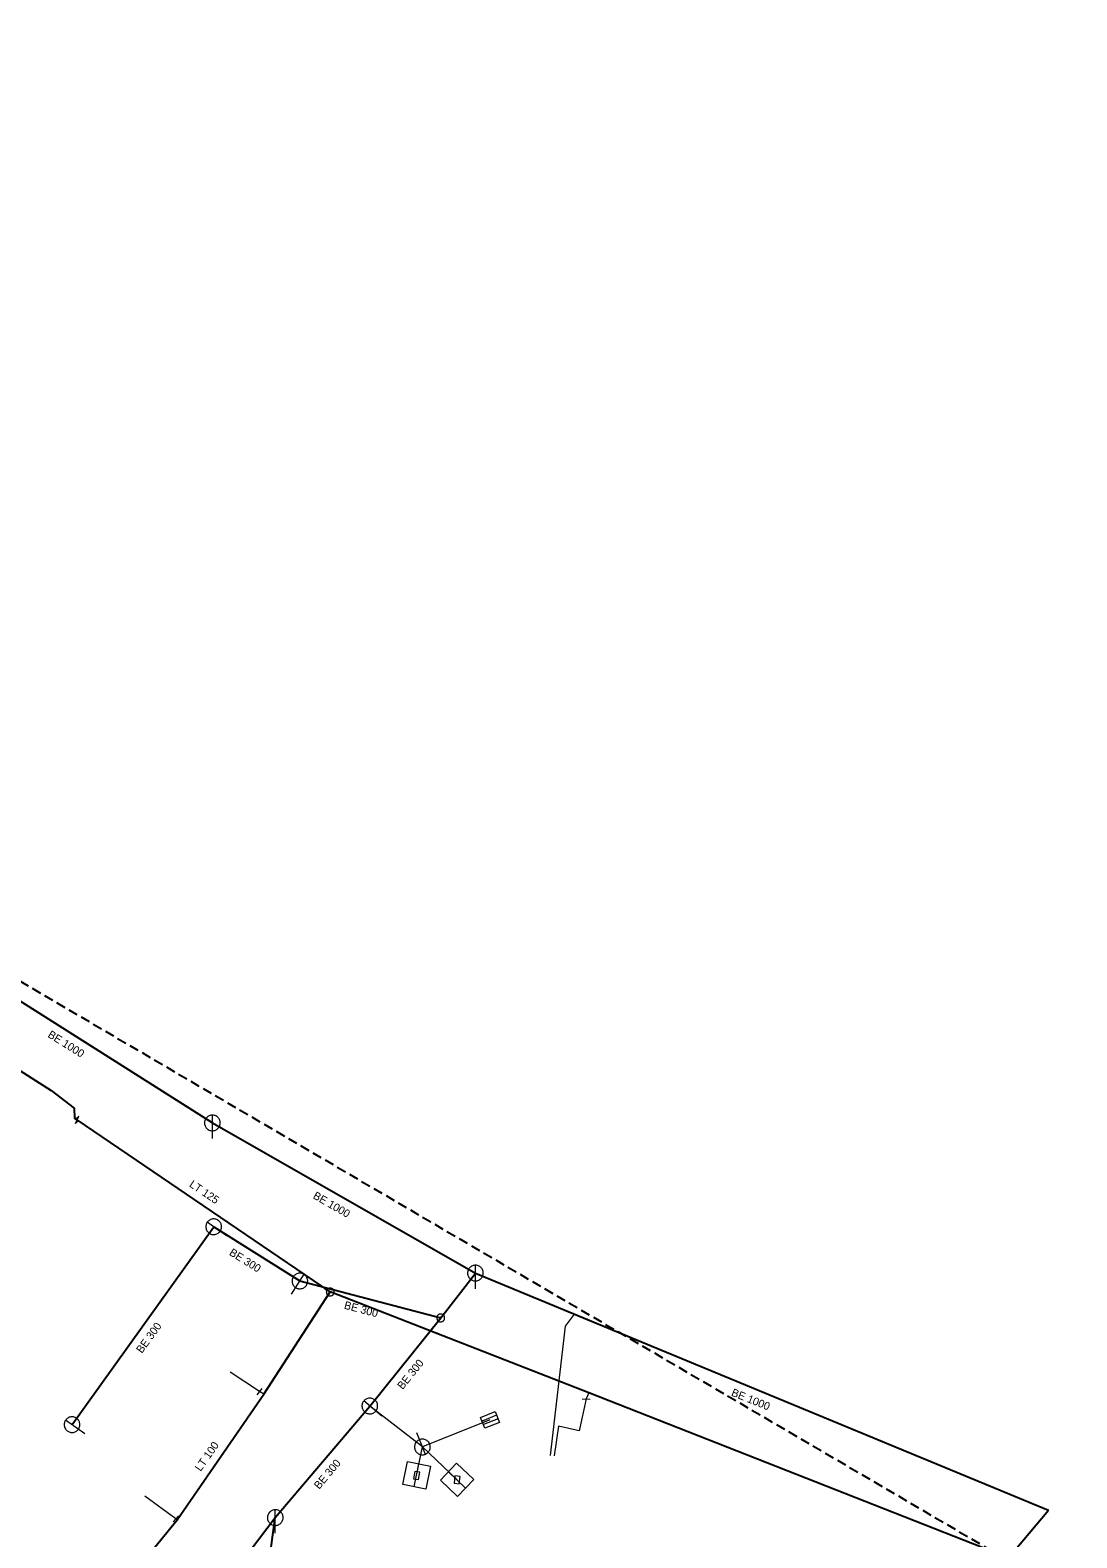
# Model space of a CAD drawing. Extents: x -791337 to -790755, y -988454 to -987923.
# Drawn here: x -791023.2 to -790890, y -988115.1 to -987923.1 of the extents above; entities that cross this region are included whole.
import ezdxf

# ---------------------------------------------------------------- set-up
doc = ezdxf.new("R2010")
doc.units = 0
doc.header["$LTSCALE"] = 0.4
doc.linetypes.add('MEDIUM_DASHED', pattern=[4.5, 3, -1.5])
for name, color, linetype, lineweight in [('1', 7, 'Continuous', 13), ('11', 7, 'Continuous', 13), ('13', 7, 'Continuous', 13), ('14', 7, 'Continuous', 25), ('17', 7, 'Continuous', 25), ('22', 7, 'Continuous', 13), ('23', 7, 'Continuous', 13), ('31', 7, 'Continuous', 13), ('34', 7, 'Continuous', 13), ('47', 7, 'Continuous', 13), ('63', 7, 'MEDIUM_DASHED', 25)]:
    doc.layers.add(name, color=color, linetype=linetype, lineweight=lineweight)

msp = doc.modelspace()

# ---------------------------------------------------------------- linework, layer by layer
at = {"layer": '1'}
for points in [[(-790974.289, -988106.68), (-790974.43, -988107.629), (-790973.78, -988107.719), (-790973.64, -988106.77)], [(-790969.16, -988107.25), (-790969.281, -988108.207), (-790968.631, -988108.287), (-790968.509, -988107.332)]]:
    msp.add_lwpolyline(points, close=True, dxfattribs=at)
at = {"layer": '11'}
for p, q in [((-790973.309, -988103.579), (-790980, -988098.359)), ((-790964.71, -988100.129), (-790973.309, -988103.579)), ((-790974.039, -988107.199), (-790973.309, -988103.579)), ((-790968.899, -988107.77), (-790973.309, -988103.579))]:
    msp.add_line(p, q, dxfattribs=at)
msp.add_lwpolyline([(-790956.991, -988104.669), (-790955.074, -988088.182), (-790953.942, -988086.649)], dxfattribs=at)
at = {"layer": '13'}
for p, q in [((-790994.059, -988096.529), (-790997.761, -988094.041)), ((-790993.489, -988096.87), (-790994.059, -988096.529)), ((-790952.1, -988096.67), (-790952.459, -988097.459)), ((-791004.699, -988112.739), (-791008.625, -988109.853))]:
    msp.add_line(p, q, dxfattribs=at)
msp.add_lwpolyline([(-790952.459, -988097.459), (-790953.335, -988101.511), (-790955.997, -988100.945), (-790956.52, -988104.695)], dxfattribs=at)
at = {"layer": '14'}
for p, q in [((-791000.039, -988062.309), (-790966.559, -988081.43)), ((-791017.9, -988100.734), (-790999.87, -988075.53)), ((-790999.87, -988075.53), (-790988.902, -988082.432)), ((-790966.559, -988081.43), (-790893.6, -988111.609)), ((-790980, -988098.359), (-790970.978, -988087.145)), ((-790995.768, -988140.376), (-790992.035, -988112.568))]:
    msp.add_line(p, q, dxfattribs=at)
at = {"layer": '14', "lineweight": 13}
msp.add_line((-791004.537, -988112.846), (-791004.699, -988112.739), dxfattribs=at)
at = {"layer": '14'}
for points in [[(-791048.694, -988062.718), (-791034.09, -988040.71), (-791000.039, -988062.309)], [(-790988.902, -988082.432), (-790970.978, -988087.145), (-790966.559, -988081.43)], [(-791003.034, -988127.09), (-790992.035, -988112.568), (-790980, -988098.359)], [(-790905.94, -988138.22), (-790903.94, -988123.91), (-790893.6, -988111.609)]]:
    msp.add_lwpolyline(points, dxfattribs=at)
at = {"layer": '17'}
msp.add_line((-790985.039, -988083.809), (-791017.239, -988061.899), dxfattribs=at)
for points in [[(-791034.776, -988049.416), (-791034.559, -988049.35), (-791029.19, -988052.69), (-791020.559, -988058.18), (-791017.64, -988060.43), (-791017.59, -988061.71), (-791017.239, -988061.899)], [(-791015.996, -988126.782), (-791014.379, -988124.914), (-791004.537, -988112.846), (-790993.489, -988096.87), (-790985.039, -988083.809)], [(-790868.789, -988131.909), (-790898.061, -988117.949), (-790952.1, -988096.67), (-790985.039, -988083.809)]]:
    msp.add_lwpolyline(points, dxfattribs=at)
at = {"layer": '22'}
for p, q in [((-791000.039, -988064.309), (-791000.038, -988061.309)), ((-790998.242, -988076.693), (-791000.682, -988074.948)), ((-790966.559, -988083.43), (-790966.558, -988080.43)), ((-790989.967, -988084.125), (-790988.369, -988081.586)), ((-790978.473, -988099.651), (-790980.762, -988097.712)), ((-790963.862, -988099.526), (-790965.718, -988100.271)), ((-791016.272, -988101.897), (-791018.712, -988100.152)), ((-790963.676, -988099.99), (-790965.532, -988100.735)), ((-790974.053, -988101.722), (-790972.936, -988104.506)), ((-790974.335, -988108.669), (-790973.741, -988105.728)), ((-790967.811, -988108.802), (-790969.986, -988106.736)), ((-790992.035, -988114.568), (-790992.034, -988111.568))]:
    msp.add_line(p, q, dxfattribs=at)
for points in [[(-790999.039, -988062.309), (-790999.044, -988062.2), (-790999.062, -988062.092), (-790999.092, -988061.986), (-790999.132, -988061.885), (-790999.184, -988061.788), (-790999.246, -988061.698), (-790999.318, -988061.615), (-790999.398, -988061.541), (-790999.486, -988061.475), (-790999.58, -988061.42), (-790999.68, -988061.375), (-790999.785, -988061.342), (-790999.892, -988061.32), (-791000.001, -988061.31), (-791000.111, -988061.312), (-791000.219, -988061.326), (-791000.326, -988061.351), (-791000.429, -988061.388), (-791000.527, -988061.437), (-791000.619, -988061.495), (-791000.705, -988061.564), (-791000.782, -988061.641), (-791000.851, -988061.727), (-791000.91, -988061.819), (-791000.958, -988061.917), (-791000.995, -988062.02), (-791001.021, -988062.127), (-791001.035, -988062.235), (-791001.038, -988062.345), (-791001.028, -988062.454), (-791001.007, -988062.561), (-791000.973, -988062.665), (-791000.929, -988062.765), (-791000.874, -988062.86), (-791000.808, -988062.948), (-791000.734, -988063.028), (-791000.651, -988063.1), (-791000.561, -988063.162), (-791000.465, -988063.214), (-791000.363, -988063.255), (-791000.258, -988063.285), (-791000.15, -988063.303), (-791000.04, -988063.309), (-790999.931, -988063.303), (-790999.823, -988063.285), (-790999.718, -988063.256), (-790999.616, -988063.215), (-790999.519, -988063.163), (-790999.429, -988063.101), (-790999.346, -988063.03), (-790999.271, -988062.95), (-790999.206, -988062.862), (-790999.15, -988062.768), (-790999.106, -988062.668), (-790999.072, -988062.564), (-790999.05, -988062.456), (-790999.04, -988062.347)], [(-790999.287, -988074.716), (-790999.379, -988074.658), (-790999.478, -988074.61), (-790999.581, -988074.572), (-790999.687, -988074.546), (-790999.796, -988074.532), (-790999.905, -988074.53), (-791000.015, -988074.54), (-791000.121, -988074.562), (-791000.226, -988074.596), (-791000.326, -988074.64), (-791000.42, -988074.695), (-791000.508, -988074.761), (-791000.589, -988074.836), (-791000.66, -988074.918), (-791000.722, -988075.009), (-791000.774, -988075.105), (-791000.816, -988075.207), (-791000.846, -988075.312), (-791000.863, -988075.42), (-791000.869, -988075.529), (-791000.863, -988075.639), (-791000.845, -988075.746), (-791000.815, -988075.852), (-791000.775, -988075.954), (-791000.723, -988076.05), (-791000.661, -988076.14), (-791000.589, -988076.223), (-791000.509, -988076.298), (-791000.421, -988076.363), (-791000.327, -988076.419), (-791000.227, -988076.464), (-791000.123, -988076.497), (-791000.016, -988076.519), (-790999.907, -988076.529), (-790999.797, -988076.527), (-790999.689, -988076.513), (-790999.582, -988076.488), (-790999.479, -988076.451), (-790999.381, -988076.403), (-790999.288, -988076.344), (-790999.203, -988076.276), (-790999.125, -988076.198), (-790999.056, -988076.112), (-790998.998, -988076.02), (-790998.95, -988075.922), (-790998.912, -988075.82), (-790998.886, -988075.713), (-790998.872, -988075.604), (-790998.87, -988075.494), (-790998.879, -988075.386), (-790998.901, -988075.278), (-790998.935, -988075.174), (-790998.979, -988075.074), (-790999.034, -988074.98), (-790999.099, -988074.892), (-790999.174, -988074.811), (-790999.257, -988074.739)], [(-790965.559, -988081.43), (-790965.564, -988081.321), (-790965.582, -988081.213), (-790965.612, -988081.107), (-790965.652, -988081.006), (-790965.704, -988080.909), (-790965.766, -988080.819), (-790965.838, -988080.736), (-790965.918, -988080.662), (-790966.006, -988080.596), (-790966.1, -988080.541), (-790966.2, -988080.496), (-790966.305, -988080.463), (-790966.412, -988080.441), (-790966.521, -988080.431), (-790966.631, -988080.433), (-790966.739, -988080.447), (-790966.846, -988080.472), (-790966.949, -988080.509), (-790967.047, -988080.558), (-790967.139, -988080.616), (-790967.225, -988080.685), (-790967.302, -988080.762), (-790967.371, -988080.848), (-790967.43, -988080.94), (-790967.478, -988081.038), (-790967.515, -988081.141), (-790967.541, -988081.248), (-790967.555, -988081.356), (-790967.558, -988081.466), (-790967.548, -988081.575), (-790967.527, -988081.682), (-790967.493, -988081.786), (-790967.449, -988081.886), (-790967.394, -988081.981), (-790967.328, -988082.069), (-790967.254, -988082.149), (-790967.171, -988082.221), (-790967.081, -988082.283), (-790966.985, -988082.335), (-790966.883, -988082.376), (-790966.778, -988082.406), (-790966.67, -988082.424), (-790966.56, -988082.43), (-790966.451, -988082.424), (-790966.343, -988082.406), (-790966.238, -988082.377), (-790966.136, -988082.336), (-790966.039, -988082.284), (-790965.949, -988082.222), (-790965.866, -988082.151), (-790965.791, -988082.071), (-790965.726, -988081.983), (-790965.67, -988081.889), (-790965.626, -988081.789), (-790965.592, -988081.685), (-790965.57, -988081.577), (-790965.56, -988081.468)], [(-790988.055, -988082.964), (-790988.002, -988082.869), (-790987.96, -988082.768), (-790987.929, -988082.662), (-790987.909, -988082.556), (-790987.901, -988082.446), (-790987.906, -988082.337), (-790987.923, -988082.228), (-790987.951, -988082.123), (-790987.99, -988082.02), (-790988.041, -988081.923), (-790988.101, -988081.832), (-790988.173, -988081.748), (-790988.251, -988081.673), (-790988.338, -988081.606), (-790988.433, -988081.549), (-790988.531, -988081.504), (-790988.635, -988081.468), (-790988.742, -988081.444), (-790988.851, -988081.433), (-790988.96, -988081.434), (-790989.07, -988081.446), (-790989.176, -988081.47), (-790989.28, -988081.506), (-790989.379, -988081.553), (-790989.472, -988081.61), (-790989.558, -988081.678), (-790989.637, -988081.754), (-790989.706, -988081.838), (-790989.766, -988081.93), (-790989.816, -988082.028), (-790989.855, -988082.13), (-790989.882, -988082.236), (-790989.898, -988082.344), (-790989.902, -988082.454), (-790989.893, -988082.563), (-790989.873, -988082.67), (-790989.841, -988082.776), (-790989.798, -988082.876), (-790989.744, -988082.971), (-790989.68, -988083.06), (-790989.607, -988083.141), (-790989.525, -988083.214), (-790989.435, -988083.278), (-790989.34, -988083.331), (-790989.239, -988083.373), (-790989.134, -988083.404), (-790989.026, -988083.424), (-790988.916, -988083.432), (-790988.807, -988083.427), (-790988.699, -988083.411), (-790988.593, -988083.383), (-790988.491, -988083.344), (-790988.394, -988083.294), (-790988.303, -988083.233), (-790988.219, -988083.163), (-790988.143, -988083.083), (-790988.076, -988082.996)], [(-790979.353, -988097.596), (-790979.44, -988097.53), (-790979.534, -988097.474), (-790979.634, -988097.428), (-790979.737, -988097.393), (-790979.845, -988097.37), (-790979.953, -988097.36), (-790980.063, -988097.361), (-790980.172, -988097.374), (-790980.279, -988097.399), (-790980.381, -988097.435), (-790980.48, -988097.482), (-790980.573, -988097.541), (-790980.659, -988097.608), (-790980.738, -988097.685), (-790980.807, -988097.77), (-790980.866, -988097.862), (-790980.916, -988097.959), (-790980.955, -988098.062), (-790980.981, -988098.168), (-790980.996, -988098.276), (-790980.999, -988098.386), (-790980.99, -988098.495), (-790980.969, -988098.603), (-790980.937, -988098.708), (-790980.893, -988098.807), (-790980.838, -988098.902), (-790980.773, -988098.991), (-790980.7, -988099.072), (-790980.617, -988099.144), (-790980.528, -988099.207), (-790980.432, -988099.26), (-790980.331, -988099.302), (-790980.226, -988099.333), (-790980.118, -988099.352), (-790980.009, -988099.359), (-790979.9, -988099.354), (-790979.791, -988099.337), (-790979.686, -988099.308), (-790979.584, -988099.269), (-790979.487, -988099.217), (-790979.396, -988099.157), (-790979.312, -988099.086), (-790979.237, -988099.006), (-790979.171, -988098.919), (-790979.115, -988098.825), (-790979.069, -988098.726), (-790979.034, -988098.622), (-790979.011, -988098.514), (-790979.001, -988098.405), (-790979.001, -988098.296), (-790979.014, -988098.187), (-790979.039, -988098.081), (-790979.074, -988097.977), (-790979.122, -988097.879), (-790979.18, -988097.786), (-790979.248, -988097.699), (-790979.324, -988097.621)], [(-790963.49, -988100.454), (-790965.346, -988101.199), (-790965.904, -988099.807), (-790964.048, -988099.062)], [(-791017.317, -988099.92), (-791017.409, -988099.862), (-791017.508, -988099.814), (-791017.611, -988099.776), (-791017.717, -988099.75), (-791017.826, -988099.736), (-791017.935, -988099.734), (-791018.045, -988099.744), (-791018.151, -988099.766), (-791018.256, -988099.8), (-791018.356, -988099.844), (-791018.45, -988099.899), (-791018.538, -988099.965), (-791018.619, -988100.04), (-791018.69, -988100.122), (-791018.752, -988100.213), (-791018.804, -988100.309), (-791018.846, -988100.411), (-791018.876, -988100.516), (-791018.893, -988100.624), (-791018.899, -988100.733), (-791018.893, -988100.843), (-791018.875, -988100.95), (-791018.845, -988101.056), (-791018.805, -988101.158), (-791018.753, -988101.254), (-791018.691, -988101.344), (-791018.619, -988101.427), (-791018.539, -988101.502), (-791018.451, -988101.567), (-791018.357, -988101.623), (-791018.257, -988101.668), (-791018.153, -988101.701), (-791018.046, -988101.723), (-791017.937, -988101.733), (-791017.827, -988101.731), (-791017.719, -988101.717), (-791017.612, -988101.692), (-791017.509, -988101.655), (-791017.411, -988101.607), (-791017.318, -988101.548), (-791017.233, -988101.48), (-791017.155, -988101.402), (-791017.086, -988101.316), (-791017.028, -988101.224), (-791016.98, -988101.126), (-791016.942, -988101.024), (-791016.916, -988100.917), (-791016.902, -988100.808), (-791016.9, -988100.698), (-791016.909, -988100.59), (-791016.931, -988100.482), (-791016.965, -988100.378), (-791017.009, -988100.278), (-791017.064, -988100.184), (-791017.129, -988100.096), (-791017.204, -988100.015), (-791017.287, -988099.943)], [(-790974.237, -988103.95), (-790974.191, -988104.049), (-790974.134, -988104.143), (-790974.066, -988104.23), (-790973.992, -988104.309), (-790973.907, -988104.38), (-790973.816, -988104.44), (-790973.719, -988104.49), (-790973.617, -988104.529), (-790973.51, -988104.558), (-790973.403, -988104.574), (-790973.293, -988104.578), (-790973.183, -988104.57), (-790973.076, -988104.55), (-790972.971, -988104.519), (-790972.87, -988104.476), (-790972.775, -988104.423), (-790972.685, -988104.36), (-790972.603, -988104.287), (-790972.53, -988104.205), (-790972.466, -988104.117), (-790972.412, -988104.021), (-790972.369, -988103.921), (-790972.337, -988103.815), (-790972.317, -988103.708), (-790972.309, -988103.599), (-790972.313, -988103.49), (-790972.329, -988103.381), (-790972.356, -988103.276), (-790972.395, -988103.173), (-790972.445, -988103.075), (-790972.504, -988102.984), (-790972.574, -988102.9), (-790972.652, -988102.823), (-790972.739, -988102.756), (-790972.833, -988102.699), (-790972.931, -988102.652), (-790973.035, -988102.616), (-790973.142, -988102.592), (-790973.25, -988102.579), (-790973.36, -988102.579), (-790973.469, -988102.591), (-790973.576, -988102.614), (-790973.68, -988102.65), (-790973.779, -988102.696), (-790973.873, -988102.753), (-790973.959, -988102.819), (-790974.039, -988102.895), (-790974.109, -988102.979), (-790974.17, -988103.07), (-790974.22, -988103.167), (-790974.26, -988103.269), (-790974.288, -988103.375), (-790974.305, -988103.483), (-790974.308, -988103.592), (-790974.301, -988103.701), (-790974.281, -988103.81), (-790974.25, -988103.915)], [(-790975.805, -988108.372), (-790975.212, -988105.432), (-790972.271, -988106.025), (-790972.864, -988108.966)], [(-790968.844, -988109.89), (-790971.019, -988107.823), (-790968.952, -988105.649), (-790966.778, -988107.715)], [(-790991.035, -988112.568), (-790991.04, -988112.459), (-790991.058, -988112.351), (-790991.088, -988112.245), (-790991.128, -988112.144), (-790991.18, -988112.047), (-790991.242, -988111.957), (-790991.314, -988111.874), (-790991.394, -988111.8), (-790991.482, -988111.734), (-790991.576, -988111.679), (-790991.676, -988111.634), (-790991.781, -988111.601), (-790991.888, -988111.579), (-790991.997, -988111.569), (-790992.107, -988111.571), (-790992.215, -988111.585), (-790992.322, -988111.61), (-790992.425, -988111.647), (-790992.523, -988111.696), (-790992.615, -988111.754), (-790992.701, -988111.823), (-790992.778, -988111.9), (-790992.847, -988111.986), (-790992.906, -988112.078), (-790992.954, -988112.176), (-790992.991, -988112.279), (-790993.017, -988112.386), (-790993.031, -988112.494), (-790993.034, -988112.604), (-790993.024, -988112.713), (-790993.003, -988112.82), (-790992.969, -988112.924), (-790992.925, -988113.024), (-790992.87, -988113.119), (-790992.804, -988113.207), (-790992.73, -988113.287), (-790992.647, -988113.359), (-790992.557, -988113.421), (-790992.461, -988113.473), (-790992.359, -988113.514), (-790992.254, -988113.544), (-790992.146, -988113.562), (-790992.036, -988113.568), (-790991.927, -988113.562), (-790991.819, -988113.544), (-790991.714, -988113.515), (-790991.612, -988113.474), (-790991.515, -988113.422), (-790991.425, -988113.36), (-790991.342, -988113.289), (-790991.267, -988113.209), (-790991.202, -988113.121), (-790991.146, -988113.027), (-790991.102, -988112.927), (-790991.068, -988112.823), (-790991.046, -988112.715), (-790991.036, -988112.606)]]:
    msp.add_lwpolyline(points, close=True, dxfattribs=at)
at = {"layer": '23'}
msp.add_line((-790985.531, -988083.379), (-790985.639, -988083.543), dxfattribs=at)
for points in [[(-790985.558, -988083.596), (-790985.682, -988083.514), (-790985.754, -988083.348), (-790985.574, -988083.35), (-790985.45, -988083.433)], [(-790984.76, -988083.421), (-790984.806, -988083.394), (-790984.855, -988083.373), (-790984.904, -988083.358), (-790984.955, -988083.347), (-790985.007, -988083.341), (-790985.06, -988083.342), (-790985.112, -988083.347), (-790985.162, -988083.358), (-790985.212, -988083.374), (-790985.26, -988083.396), (-790985.306, -988083.422), (-790985.348, -988083.453), (-790985.387, -988083.488), (-790985.421, -988083.526), (-790985.452, -988083.568), (-790985.479, -988083.615), (-790985.499, -988083.661), (-790985.516, -988083.713), (-790985.527, -988083.762), (-790985.533, -988083.815), (-790985.531, -988083.868), (-790985.526, -988083.92), (-790985.514, -988083.972), (-790985.499, -988084.021), (-790985.478, -988084.068), (-790985.45, -988084.114), (-790985.42, -988084.155), (-790985.385, -988084.194), (-790985.345, -988084.229), (-790985.304, -988084.26), (-790985.259, -988084.286), (-790985.21, -988084.308), (-790985.16, -988084.324), (-790985.11, -988084.335), (-790985.058, -988084.339), (-790985.006, -988084.339), (-790984.953, -988084.334), (-790984.901, -988084.323), (-790984.852, -988084.306)], [(-790985.516, -988083.713), (-790985.527, -988083.762), (-790985.533, -988083.815), (-790985.531, -988083.868), (-790985.526, -988083.92), (-790985.514, -988083.972), (-790985.499, -988084.021), (-790985.478, -988084.068), (-790985.45, -988084.114), (-790985.42, -988084.155), (-790985.385, -988084.194), (-790985.345, -988084.229), (-790985.304, -988084.26), (-790985.259, -988084.286), (-790985.21, -988084.308), (-790985.16, -988084.324), (-790985.11, -988084.335), (-790985.058, -988084.339), (-790985.006, -988084.339), (-790984.953, -988084.334), (-790984.901, -988084.323), (-790984.852, -988084.306), (-790984.805, -988084.286), (-790984.759, -988084.259), (-790984.717, -988084.229), (-790984.678, -988084.192), (-790984.644, -988084.154), (-790984.613, -988084.112), (-790984.587, -988084.067), (-790984.565, -988084.019), (-790984.549, -988083.969), (-790984.539, -988083.917), (-790984.533, -988083.865), (-790984.533, -988083.814), (-790984.54, -988083.761), (-790984.549, -988083.71), (-790984.566, -988083.661), (-790984.587, -988083.612), (-790984.614, -988083.567), (-790984.645, -988083.525)], [(-790984.852, -988084.306), (-790984.805, -988084.286), (-790984.759, -988084.259), (-790984.717, -988084.229), (-790984.678, -988084.192), (-790984.644, -988084.154), (-790984.613, -988084.112), (-790984.587, -988084.067), (-790984.565, -988084.019), (-790984.549, -988083.969), (-790984.539, -988083.917), (-790984.533, -988083.865), (-790984.533, -988083.814), (-790984.54, -988083.761), (-790984.549, -988083.71), (-790984.566, -988083.661), (-790984.587, -988083.612), (-790984.614, -988083.567), (-790984.645, -988083.525), (-790984.681, -988083.487), (-790984.719, -988083.452), (-790984.76, -988083.421), (-790984.806, -988083.394), (-790984.855, -988083.373), (-790984.904, -988083.358), (-790984.955, -988083.347), (-790985.007, -988083.341), (-790985.06, -988083.342), (-790985.112, -988083.347), (-790985.162, -988083.358), (-790985.212, -988083.374), (-790985.26, -988083.396), (-790985.306, -988083.422), (-790985.348, -988083.453), (-790985.387, -988083.488), (-790985.421, -988083.526), (-790985.452, -988083.568), (-790985.479, -988083.615), (-790985.499, -988083.661), (-790985.516, -988083.713)], [(-790984.645, -988083.525), (-790984.681, -988083.487), (-790984.719, -988083.452), (-790984.76, -988083.421)]]:
    msp.add_lwpolyline(points, dxfattribs=at)
at = {"layer": '31'}
for points in [[(-790970.659, -988086.759), (-790970.701, -988086.729), (-790970.746, -988086.702), (-790970.793, -988086.68), (-790970.842, -988086.663), (-790970.894, -988086.652), (-790970.946, -988086.646), (-790970.998, -988086.646), (-790971.05, -988086.651), (-790971.101, -988086.66), (-790971.151, -988086.676), (-790971.2, -988086.697), (-790971.245, -988086.723), (-790971.288, -988086.752), (-790971.327, -988086.787), (-790971.363, -988086.826), (-790971.393, -988086.868), (-790971.42, -988086.913), (-790971.442, -988086.961), (-790971.459, -988087.009), (-790971.47, -988087.061), (-790971.476, -988087.113), (-790971.477, -988087.166), (-790971.472, -988087.218), (-790971.462, -988087.269), (-790971.446, -988087.318), (-790971.425, -988087.367), (-790971.4, -988087.413), (-790971.37, -988087.455), (-790971.335, -988087.494), (-790971.296, -988087.53), (-790971.254, -988087.56), (-790971.209, -988087.587), (-790971.162, -988087.61), (-790971.113, -988087.626), (-790971.061, -988087.637), (-790971.009, -988087.644), (-790970.957, -988087.645), (-790970.905, -988087.64), (-790970.853, -988087.629), (-790970.804, -988087.613), (-790970.755, -988087.592), (-790970.71, -988087.568), (-790970.667, -988087.537), (-790970.628, -988087.502), (-790970.592, -988087.463), (-790970.562, -988087.421), (-790970.535, -988087.376), (-790970.513, -988087.33), (-790970.496, -988087.28), (-790970.485, -988087.228), (-790970.478, -988087.176), (-790970.478, -988087.125), (-790970.483, -988087.072), (-790970.493, -988087.021), (-790970.509, -988086.971), (-790970.53, -988086.922), (-790970.555, -988086.878), (-790970.585, -988086.834), (-790970.62, -988086.795)], [(-790970.925, -988087.081), (-790970.932, -988087.076), (-790970.94, -988087.072), (-790970.947, -988087.068), (-790970.955, -988087.066), (-790970.964, -988087.064), (-790970.972, -988087.063), (-790970.981, -988087.062), (-790970.989, -988087.063), (-790970.998, -988087.065), (-790971.006, -988087.068), (-790971.014, -988087.071), (-790971.022, -988087.075), (-790971.028, -988087.08), (-790971.035, -988087.085), (-790971.041, -988087.092), (-790971.046, -988087.099), (-790971.05, -988087.107), (-790971.054, -988087.114), (-790971.056, -988087.122), (-790971.058, -988087.131), (-790971.059, -988087.139), (-790971.06, -988087.148), (-790971.059, -988087.156), (-790971.057, -988087.165), (-790971.054, -988087.173), (-790971.051, -988087.181), (-790971.047, -988087.189), (-790971.042, -988087.195), (-790971.037, -988087.202), (-790971.03, -988087.208), (-790971.023, -988087.213), (-790971.015, -988087.217), (-790971.008, -988087.221), (-790971, -988087.223), (-790970.991, -988087.225), (-790970.983, -988087.227), (-790970.974, -988087.227), (-790970.966, -988087.226), (-790970.957, -988087.224), (-790970.949, -988087.221), (-790970.941, -988087.218), (-790970.933, -988087.214), (-790970.927, -988087.209), (-790970.92, -988087.204), (-790970.914, -988087.197), (-790970.909, -988087.19), (-790970.905, -988087.182), (-790970.901, -988087.175), (-790970.899, -988087.167), (-790970.897, -988087.158), (-790970.895, -988087.15), (-790970.895, -988087.141), (-790970.896, -988087.133), (-790970.898, -988087.124), (-790970.901, -988087.116), (-790970.904, -988087.108), (-790970.908, -988087.1), (-790970.913, -988087.094), (-790970.918, -988087.087)]]:
    msp.add_lwpolyline(points, close=True, dxfattribs=at)
at = {"layer": '34'}
for p, q in [((-790993.748, -988096.136), (-790994.37, -988096.92)), ((-790952.958, -988097.435), (-790951.959, -988097.483)), ((-791004.369, -988112.362), (-791005.028, -988113.114))]:
    msp.add_line(p, q, dxfattribs=at)
at = {"layer": '47'}
msp.add_line((-791017.439, -988062.367), (-791017.072, -988062.012), dxfattribs=at)
msp.add_lwpolyline([(-791017.439, -988062.367), (-791017.038, -988061.43), (-791017.405, -988061.785)], dxfattribs=at)
at = {"layer": '63'}
msp.add_lwpolyline([(-791231.02, -987923.132), (-790755.118, -988202.253), (-790755.118, -988202.253), (-790903.053, -988400.429), (-790903.053, -988400.429), (-791331.504, -988073.857), (-791331.504, -988073.857)], close=True, dxfattribs=at)

# ---------------------------------------------------------------- texts
at = {"layer": '1'}
for s, rotation, p in [('BE 1000 ', 328, (-791021.083, -988051.311)), ('LT 125', 326, (-791003.065, -988070.351)), ('BE 1000 ', 330, (-790987.323, -988071.857)), ('BE 300', 328, (-790997.982, -988079.063)), ('BE 300', 345, (-790983.346, -988085.945)), ('BE 300', 54, (-791009.015, -988091.726)), ('BE 300', 51, (-790975.821, -988096.334)), ('BE 1000 ', 338, (-790934.072, -988097.016)), ('LT 100', 55, (-791001.529, -988106.764)), ('BE 300', 50, (-790986.441, -988109.036))]:
    msp.add_text(s, height=1, rotation=rotation, dxfattribs=at).set_placement(p)

doc.saveas('drawing.dxf')
